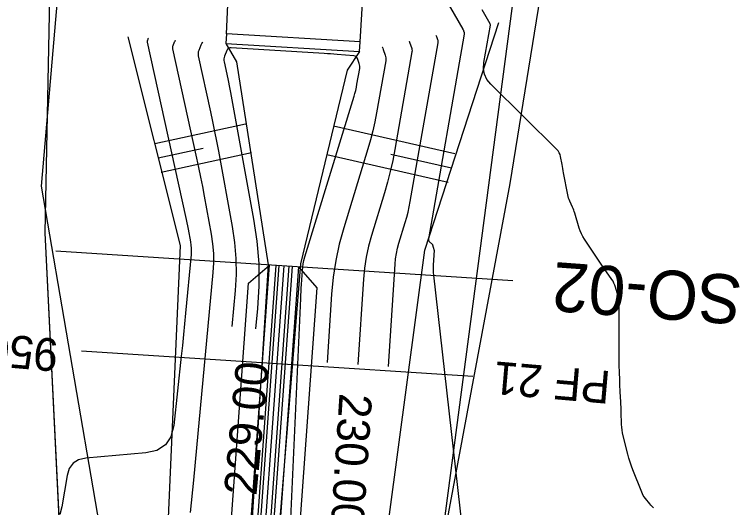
# Model space of a CAD drawing. Extents: x -534410 to -534262, y -1190162 to -1189584.
# Drawn here: x -534369.58 to -534347.56, y -1189635.21 to -1189620.13 of the extents above; entities that cross this region are included whole.
import ezdxf

# ---------------------------------------------------------------- set-up
doc = ezdxf.new("R2010")
doc.units = 0
for name, color, linetype in [('30', 7, 'Continuous'), ('31', 7, 'Continuous'), ('40', 7, 'Continuous'), ('_linie', 7, 'Continuous'), ('_N_osa', 7, 'Continuous'), ('_N_tenká', 7, 'Continuous'), ('_N_tenká_velmi', 7, 'Continuous'), ('_N_text', 7, 'Continuous'), ('_tenka', 7, 'Continuous'), ('_velmi_tenka', 7, 'Continuous'), ('Default', 7, 'Continuous'), ('Hranice parcel', 7, 'Continuous')]:
    doc.layers.add(name, color=color, linetype=linetype)

msp = doc.modelspace()

# ---------------------------------------------------------------- linework, layer by layer
at = {"layer": '30'}
for points in [[(-534356.895, -1189618.808), (-534355.874, -1189620.574), (-534355.867, -1189620.586), (-534355.861, -1189620.598), (-534355.855, -1189620.611), (-534355.85, -1189620.624), (-534355.832, -1189620.675), (-534355.828, -1189620.688), (-534355.826, -1189620.701), (-534355.826, -1189620.715), (-534355.827, -1189620.728), (-534356.924, -1189626.99), (-534356.925, -1189627.013), (-534356.921, -1189627.034), (-534356.912, -1189627.053), (-534356.898, -1189627.07), (-534356.802, -1189627.166), (-534356.799, -1189627.168), (-534356.797, -1189627.171), (-534356.796, -1189627.174), (-534356.795, -1189627.178), (-534356.783, -1189627.244), (-534356.781, -1189627.25), (-534356.779, -1189627.255), (-534356.773, -1189627.268), (-534356.771, -1189627.276), (-534356.755, -1189627.329), (-534356.754, -1189627.334), (-534356.753, -1189627.34), (-534356.779, -1189627.795), (-534356.781, -1189627.872), (-534356.781, -1189627.949), (-534356.777, -1189628.025), (-534356.77, -1189628.102), (-534355.551, -1189638.836)], [(-534364.199, -1189635.366), (-534364.1, -1189634.375), (-534364.006, -1189633.383), (-534363.504, -1189628.024), (-534363.486, -1189627.729), (-534363.489, -1189627.436), (-534363.512, -1189627.143), (-534363.555, -1189626.851), (-534363.768, -1189625.686), (-534363.823, -1189625.395), (-534363.88, -1189625.104), (-534363.94, -1189624.814), (-534364.002, -1189624.524), (-534364.738, -1189621.183), (-534364.742, -1189621.155), (-534364.742, -1189621.127), (-534364.737, -1189621.1), (-534364.728, -1189621.073), (-534364.684, -1189620.966), (-534364.671, -1189620.94), (-534364.657, -1189620.915), (-534364.655, -1189620.913)], [(-534357.514, -1189620.943), (-534357.514, -1189620.944), (-534357.5, -1189620.975), (-534357.487, -1189621.008), (-534357.44, -1189621.138), (-534357.431, -1189621.171), (-534357.426, -1189621.204), (-534357.425, -1189621.237), (-534357.429, -1189621.271), (-534357.952, -1189624.26), (-534358.016, -1189624.595), (-534358.09, -1189624.928), (-534358.175, -1189625.258), (-534358.27, -1189625.585), (-534358.669, -1189626.89), (-534358.759, -1189627.218), (-534358.83, -1189627.55), (-534358.881, -1189627.885), (-534358.913, -1189628.224), (-534359.084, -1189630.834)], [(-534361.638, -1189646.761), (-534360.829, -1189628.817), (-534360.824, -1189628.711), (-534360.819, -1189628.604), (-534360.813, -1189628.497), (-534360.806, -1189628.391), (-534360.778, -1189627.965), (-534360.768, -1189627.859), (-534360.752, -1189627.754), (-534360.73, -1189627.65), (-534360.702, -1189627.547), (-534359.197, -1189622.632), (-534359.171, -1189622.541), (-534359.148, -1189622.449), (-534359.127, -1189622.357), (-534359.109, -1189622.264), (-534359.025, -1189621.785), (-534359.021, -1189621.745), (-534359.022, -1189621.705), (-534359.028, -1189621.666), (-534359.039, -1189621.628), (-534359.094, -1189621.475), (-534359.112, -1189621.441), (-534359.135, -1189621.416), (-534359.166, -1189621.399), (-534359.203, -1189621.392), (-534359.717, -1189621.351), (-534359.816, -1189621.343), (-534359.915, -1189621.336), (-534360.014, -1189621.329), (-534360.113, -1189621.323), (-534362.956, -1189621.145), (-534362.999, -1189621.148), (-534363.036, -1189621.162), (-534363.064, -1189621.188), (-534363.086, -1189621.226), (-534363.158, -1189621.4), (-534363.173, -1189621.443), (-534363.18, -1189621.488), (-534363.181, -1189621.533), (-534363.174, -1189621.578), (-534363.059, -1189622.102), (-534363.037, -1189622.204), (-534363.016, -1189622.307), (-534362.995, -1189622.41), (-534362.976, -1189622.514), (-534362.268, -1189626.386), (-534362.168, -1189627.067), (-534362.114, -1189627.75), (-534362.108, -1189628.435), (-534362.149, -1189629.123), (-534362.207, -1189629.742)]]:
    msp.add_lwpolyline(points, dxfattribs=at)
at = {"layer": '31'}
for points in [[(-534350.045, -1189635.224), (-534350.082, -1189635.184), (-534350.118, -1189635.143), (-534350.153, -1189635.1), (-534350.29, -1189634.93), (-534350.323, -1189634.886), (-534350.352, -1189634.84), (-534350.377, -1189634.793), (-534350.399, -1189634.743), (-534350.67, -1189634.059), (-534350.715, -1189633.941), (-534350.756, -1189633.822), (-534350.793, -1189633.701), (-534350.826, -1189633.579), (-534350.968, -1189633.017), (-534350.988, -1189632.93), (-534351.002, -1189632.843), (-534351.012, -1189632.755), (-534351.017, -1189632.667), (-534351.028, -1189632.288), (-534351.03, -1189632.211), (-534351.033, -1189632.134), (-534351.037, -1189632.057), (-534351.041, -1189631.98), (-534351.059, -1189631.673), (-534351.064, -1189631.596), (-534351.067, -1189631.519), (-534351.07, -1189631.442), (-534351.073, -1189631.365), (-534351.084, -1189631.013), (-534351.086, -1189630.929), (-534351.088, -1189630.844), (-534351.089, -1189630.76), (-534351.089, -1189630.676), (-534351.089, -1189628.976), (-534351.091, -1189628.911), (-534351.098, -1189628.846), (-534351.11, -1189628.782), (-534351.127, -1189628.719), (-534351.202, -1189628.467), (-534351.223, -1189628.405), (-534351.249, -1189628.345), (-534351.279, -1189628.288), (-534351.314, -1189628.233), (-534351.617, -1189627.792), (-534351.68, -1189627.7), (-534351.743, -1189627.609), (-534351.805, -1189627.517), (-534351.867, -1189627.425), (-534352.15, -1189627.003), (-534352.201, -1189626.922), (-534352.244, -1189626.838), (-534352.281, -1189626.751), (-534352.312, -1189626.661), (-534352.448, -1189626.207), (-534352.463, -1189626.159), (-534352.48, -1189626.112), (-534352.498, -1189626.066), (-534352.519, -1189626.02), (-534352.603, -1189625.837), (-534352.622, -1189625.791), (-534352.639, -1189625.744), (-534352.652, -1189625.696), (-534352.663, -1189625.647), (-534352.79, -1189624.969), (-534352.802, -1189624.907), (-534352.813, -1189624.844), (-534352.825, -1189624.782), (-534352.836, -1189624.72), (-534352.883, -1189624.471), (-534352.898, -1189624.411), (-534352.922, -1189624.356), (-534352.955, -1189624.304), (-534352.996, -1189624.258), (-534355.017, -1189622.26), (-534355.134, -1189622.116), (-534355.208, -1189621.959), (-534355.239, -1189621.787), (-534355.227, -1189621.602), (-534355.026, -1189620.457), (-534355.026, -1189620.454), (-534355.026, -1189620.45), (-534355.026, -1189620.447), (-534355.027, -1189620.444), (-534355.033, -1189620.428), (-534355.036, -1189620.422), (-534355.038, -1189620.419), (-534355.285, -1189619.991)], [(-534365.488, -1189620.854), (-534365.488, -1189620.855), (-534365.495, -1189620.866), (-534365.5, -1189620.877), (-534365.519, -1189620.924), (-534365.523, -1189620.935), (-534365.525, -1189620.947), (-534365.525, -1189620.959), (-534365.523, -1189620.971), (-534364.347, -1189626.308), (-534364.327, -1189626.405), (-534364.307, -1189626.501), (-534364.288, -1189626.598), (-534364.269, -1189626.695), (-534364.198, -1189627.084), (-534364.184, -1189627.181), (-534364.176, -1189627.279), (-534364.175, -1189627.376), (-534364.181, -1189627.475), (-534364.349, -1189629.261), (-534364.38, -1189629.592), (-534364.413, -1189629.922), (-534364.447, -1189630.252), (-534364.482, -1189630.582), (-534364.712, -1189632.702), (-534364.797, -1189633.044), (-534364.968, -1189633.297), (-534365.226, -1189633.463), (-534365.569, -1189633.541), (-534367.402, -1189633.701), (-534367.62, -1189633.749), (-534367.788, -1189633.853), (-534367.905, -1189634.012), (-534367.971, -1189634.226), (-534368.133, -1189635.192), (-534368.19, -1189635.425)], [(-534358.147, -1189630.895), (-534357.942, -1189627.768), (-534357.927, -1189627.604), (-534357.902, -1189627.442), (-534357.868, -1189627.281), (-534357.824, -1189627.122), (-534357.631, -1189626.49), (-534357.585, -1189626.331), (-534357.544, -1189626.171), (-534357.508, -1189626.01), (-534357.477, -1189625.848), (-534356.628, -1189621), (-534356.625, -1189620.976), (-534356.626, -1189620.953), (-534356.629, -1189620.929), (-534356.636, -1189620.907), (-534356.669, -1189620.816), (-534356.678, -1189620.793), (-534356.687, -1189620.771), (-534356.688, -1189620.771)], [(-534362.929, -1189629.674), (-534362.826, -1189628.573), (-534362.797, -1189628.082), (-534362.802, -1189627.593), (-534362.84, -1189627.105), (-534362.912, -1189626.619), (-534363.334, -1189624.309), (-534363.39, -1189624.007), (-534363.45, -1189623.706), (-534363.512, -1189623.405), (-534363.576, -1189623.105), (-534363.953, -1189621.395), (-534363.959, -1189621.351), (-534363.959, -1189621.308), (-534363.952, -1189621.265), (-534363.938, -1189621.222), (-534363.868, -1189621.054), (-534363.848, -1189621.013), (-534363.826, -1189620.975), (-534363.823, -1189620.971)], [(-534358.341, -1189621.116), (-534358.34, -1189621.117), (-534358.322, -1189621.158), (-534358.306, -1189621.2), (-534358.245, -1189621.369), (-534358.232, -1189621.412), (-534358.226, -1189621.455), (-534358.225, -1189621.498), (-534358.23, -1189621.542), (-534358.508, -1189623.132), (-534358.561, -1189623.411), (-534358.623, -1189623.687), (-534358.693, -1189623.962), (-534358.772, -1189624.235), (-534359.514, -1189626.658), (-534359.65, -1189627.155), (-534359.758, -1189627.658), (-534359.835, -1189628.166), (-534359.884, -1189628.679), (-534360.021, -1189630.773)]]:
    msp.add_lwpolyline(points, dxfattribs=at)
at = {"layer": '_linie'}
for points in [[(-534366.12, -1189620.81), (-534364.52, -1189627.2), (-534365.69, -1189653.8), (-534366.76, -1189684.81), (-534368.14, -1189748.73), (-534368.38, -1189779.14), (-534368.65, -1189820.64), (-534368.59, -1189847.58), (-534367.2, -1189913.8)], [(-534363.12, -1189621.02), (-534362.79, -1189621.58), (-534361.82, -1189627.79), (-534363.46, -1189653.55), (-534365.47, -1189684.77), (-534366.65, -1189748.83), (-534366.75, -1189779.47), (-534366.9, -1189820.47), (-534366.95, -1189846.72), (-534366.338, -1189888.804), (-534363.85, -1189911.95), (-534357.07, -1189929.19), (-534352.334, -1189940.856)], [(-534359.03, -1189621.26), (-534359.41, -1189621.83), (-534360.84, -1189627.76), (-534362.92, -1189653.56), (-534364.64, -1189685), (-534365.94, -1189748.9), (-534366.02, -1189779.52), (-534366.03, -1189820.5), (-534366.48, -1189846.73), (-534365.511, -1189888.873), (-534362.72, -1189912.12), (-534356.62, -1189928.64), (-534351.589, -1189940.594)]]:
    msp.add_lwpolyline(points, dxfattribs=at)
at = {"layer": '_N_osa'}
msp.add_lwpolyline([(-534351.95, -1189940.722), (-534356.845, -1189928.915), (-534363.285, -1189912.035), (-534365.925, -1189888.838), (-534366.715, -1189846.725), (-534366.465, -1189820.485), (-534366.385, -1189779.495), (-534366.295, -1189748.865), (-534365.055, -1189684.885), (-534363.19, -1189653.555), (-534361.333, -1189627.822)], dxfattribs=at)
at = {"layer": '_N_tenká'}
msp.add_line((-534354.347, -1189628.277), (-534368.317, -1189627.366), dxfattribs=at)
for points in [[(-534352.92, -1189941.124), (-534357.821, -1189929.303), (-534364.313, -1189912.285), (-534366.973, -1189888.908), (-534367.765, -1189846.73), (-534367.515, -1189820.479), (-534367.435, -1189779.492), (-534367.345, -1189748.853), (-534366.104, -1189684.844), (-534364.238, -1189653.486), (-534362.424, -1189628.352), (-534361.782, -1189627.792)], [(-534350.98, -1189940.319), (-534355.869, -1189928.527), (-534362.257, -1189911.785), (-534364.876, -1189888.769), (-534365.665, -1189846.72), (-534365.415, -1189820.491), (-534365.335, -1189779.498), (-534365.245, -1189748.877), (-534364.006, -1189684.926), (-534362.142, -1189653.624), (-534360.329, -1189628.488), (-534360.884, -1189627.851)]]:
    msp.add_lwpolyline(points, dxfattribs=at)
at = {"layer": '_N_tenká_velmi'}
for points in [[(-534352.366, -1189940.894), (-534357.263, -1189929.081), (-534363.726, -1189912.142), (-534366.374, -1189888.868), (-534367.165, -1189846.727), (-534366.915, -1189820.482), (-534366.835, -1189779.494), (-534366.745, -1189748.86), (-534365.505, -1189684.867), (-534363.639, -1189653.525), (-534361.782, -1189627.792)], [(-534352.181, -1189940.817), (-534357.077, -1189929.007), (-534363.53, -1189912.095), (-534366.174, -1189888.855), (-534366.965, -1189846.726), (-534366.715, -1189820.484), (-534366.635, -1189779.494), (-534366.545, -1189748.862), (-534365.305, -1189684.875), (-534363.439, -1189653.539), (-534361.583, -1189627.805)], [(-534352.089, -1189940.779), (-534356.984, -1189928.97), (-534363.432, -1189912.071), (-534366.074, -1189888.848), (-534366.865, -1189846.726), (-534366.615, -1189820.484), (-534366.535, -1189779.495), (-534366.445, -1189748.863), (-534365.205, -1189684.879), (-534363.34, -1189653.545), (-534361.483, -1189627.812)], [(-534351.812, -1189940.664), (-534356.706, -1189928.86), (-534363.138, -1189911.999), (-534365.775, -1189888.828), (-534366.565, -1189846.724), (-534366.315, -1189820.486), (-534366.235, -1189779.495), (-534366.145, -1189748.867), (-534364.905, -1189684.891), (-534363.04, -1189653.565), (-534361.184, -1189627.831)], [(-534351.719, -1189940.626), (-534356.613, -1189928.823), (-534363.04, -1189911.975), (-534365.675, -1189888.822), (-534366.465, -1189846.724), (-534366.215, -1189820.486), (-534366.135, -1189779.496), (-534366.045, -1189748.868), (-534364.805, -1189684.895), (-534362.941, -1189653.571), (-534361.084, -1189627.838)], [(-534351.534, -1189940.549), (-534356.427, -1189928.749), (-534362.844, -1189911.928), (-534365.475, -1189888.808), (-534366.265, -1189846.723), (-534366.015, -1189820.488), (-534365.935, -1189779.496), (-534365.845, -1189748.87), (-534364.605, -1189684.903), (-534362.741, -1189653.585), (-534360.884, -1189627.851)]]:
    msp.add_lwpolyline(points, dxfattribs=at)
at = {"layer": '_N_text'}
msp.add_lwpolyline([(-534355.562, -1189631.204), (-534367.537, -1189630.423)], dxfattribs=at)
at = {"layer": '_tenka'}
for points in [[(-534349.13, -1189939.73), (-534354.63, -1189926.96), (-534362.03, -1189907.65), (-534364.521, -1189888.74), (-534364.47, -1189846.64), (-534364.29, -1189820.63), (-534364.22, -1189780.69), (-534363.18, -1189749.38), (-534362.5, -1189685.39), (-534360.27, -1189651.6), (-534357.03, -1189627.34), (-534354.77, -1189620.37)], [(-534366.12, -1189620.81), (-534364.52, -1189627.2), (-534365.69, -1189653.8), (-534366.76, -1189684.81), (-534368.14, -1189748.73), (-534368.38, -1189779.14), (-534368.65, -1189820.64), (-534368.59, -1189847.58), (-534367.2, -1189913.8)], [(-534366.12, -1189620.81), (-534364.52, -1189627.2), (-534365.69, -1189653.8), (-534366.76, -1189684.81), (-534368.14, -1189748.73), (-534368.38, -1189779.14), (-534368.65, -1189820.64), (-534368.59, -1189847.58), (-534367.2, -1189913.8)], [(-534363.12, -1189621.02), (-534362.79, -1189621.58), (-534361.82, -1189627.79), (-534363.46, -1189653.55), (-534365.47, -1189684.77), (-534366.65, -1189748.83), (-534366.75, -1189779.47), (-534366.9, -1189820.47), (-534366.95, -1189846.72), (-534366.338, -1189888.804), (-534363.85, -1189911.95), (-534357.07, -1189929.19), (-534352.334, -1189940.856)], [(-534363.12, -1189621.02), (-534362.79, -1189621.58), (-534361.82, -1189627.79), (-534363.46, -1189653.55), (-534365.47, -1189684.77), (-534366.65, -1189748.83), (-534366.75, -1189779.47), (-534366.9, -1189820.47), (-534366.95, -1189846.72), (-534366.338, -1189888.804), (-534363.85, -1189911.95), (-534357.07, -1189929.19), (-534352.334, -1189940.856)], [(-534359.03, -1189621.26), (-534359.41, -1189621.83), (-534360.84, -1189627.76), (-534362.92, -1189653.56), (-534364.64, -1189685), (-534365.94, -1189748.9), (-534366.02, -1189779.52), (-534366.03, -1189820.5), (-534366.48, -1189846.73), (-534365.511, -1189888.873), (-534362.72, -1189912.12), (-534356.62, -1189928.64), (-534351.589, -1189940.594)], [(-534359.03, -1189621.26), (-534359.41, -1189621.83), (-534360.84, -1189627.76), (-534362.92, -1189653.56), (-534364.64, -1189685), (-534365.94, -1189748.9), (-534366.02, -1189779.52), (-534366.03, -1189820.5), (-534366.48, -1189846.73), (-534365.511, -1189888.873), (-534362.72, -1189912.12), (-534356.62, -1189928.64), (-534351.589, -1189940.594)], [(-534368.65, -1189626.81), (-534368.65, -1189626.81), (-534367.31, -1189654.04), (-534367.67, -1189685.23), (-534369.56, -1189748.93), (-534369.48, -1189778.6), (-534369.45, -1189820.62), (-534369.45, -1189847.87), (-534371.206, -1189896.071), (-534372.39, -1189914.47)]]:
    msp.add_lwpolyline(points, dxfattribs=at)
at = {"layer": '_velmi_tenka'}
for p, q in [((-534365.288, -1189624.076), (-534362.522, -1189623.472)), ((-534356.116, -1189624.394), (-534359.829, -1189623.543)), ((-534365.192, -1189624.515), (-534363.809, -1189624.214)), ((-534365.096, -1189624.955), (-534362.33, -1189624.352)), ((-534356.317, -1189625.271), (-534360.029, -1189624.421)), ((-534356.217, -1189624.832), (-534358.073, -1189624.407))]:
    msp.add_line(p, q, dxfattribs=at)
at = {"layer": 'Default'}
for p, q in [((-534368.495, -1189618.669), (-534368.65, -1189626.81)), ((-534363.102, -1189620.721), (-534363.002, -1189618.721)), ((-534359.012, -1189620.961), (-534358.886, -1189618.961)), ((-534363.102, -1189620.721), (-534363.12, -1189621.02)), ((-534359.012, -1189620.961), (-534363.102, -1189620.721)), ((-534359.03, -1189621.26), (-534359.012, -1189620.961)), ((-534368.65, -1189626.81), (-534367.31, -1189654.04))]:
    msp.add_line(p, q, dxfattribs=at)
for points in [[(-534349.13, -1189939.73), (-534354.63, -1189926.96), (-534362.03, -1189907.65), (-534364.521, -1189888.74), (-534364.47, -1189846.64), (-534364.29, -1189820.63), (-534364.22, -1189780.69), (-534363.18, -1189749.38), (-534362.5, -1189685.39), (-534360.27, -1189651.6), (-534357.03, -1189627.34), (-534354.77, -1189620.37)], [(-534363.12, -1189621.02), (-534359.03, -1189621.26)]]:
    msp.add_lwpolyline(points, dxfattribs=at)
at = {"layer": 'Hranice parcel'}
msp.add_line((-534366.56, -1189638.19), (-534368.76, -1189625.38), dxfattribs=at)
for points in [[(-534368.76, -1189625.38), (-534365.237, -1189584.47)], [(-534356.61, -1189636.93), (-534352.14, -1189603.1), (-534349.757, -1189584.47)], [(-534347.83, -1189584.47), (-534354.43, -1189625.3), (-534356.61, -1189636.93)]]:
    msp.add_lwpolyline(points, dxfattribs=at)

# ---------------------------------------------------------------- texts
at = {"layer": '40'}
for s, rotation, p in [('229.00', 84.6494, (-534362.185, -1189634.869)), ('230.00', 266.2644, (-534359.641, -1189631.698))]:
    msp.add_text(s, height=1, rotation=rotation, dxfattribs=at).set_placement(p)
at = {"layer": '_N_text'}
for s, height, rotation, p in [('KÚ, SO-02', 1.5, 175.8075, (-534343.402, -1189628.407)), ('950', 1, 175.0404, (-534368.21, -1189630.061)), ('PF 21', 1, 175.0879, (-534351.324, -1189631.044))]:
    msp.add_text(s, height=height, rotation=rotation, dxfattribs=at).set_placement(p)

doc.saveas('drawing.dxf')
